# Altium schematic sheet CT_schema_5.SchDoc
size 188 x 165 mm
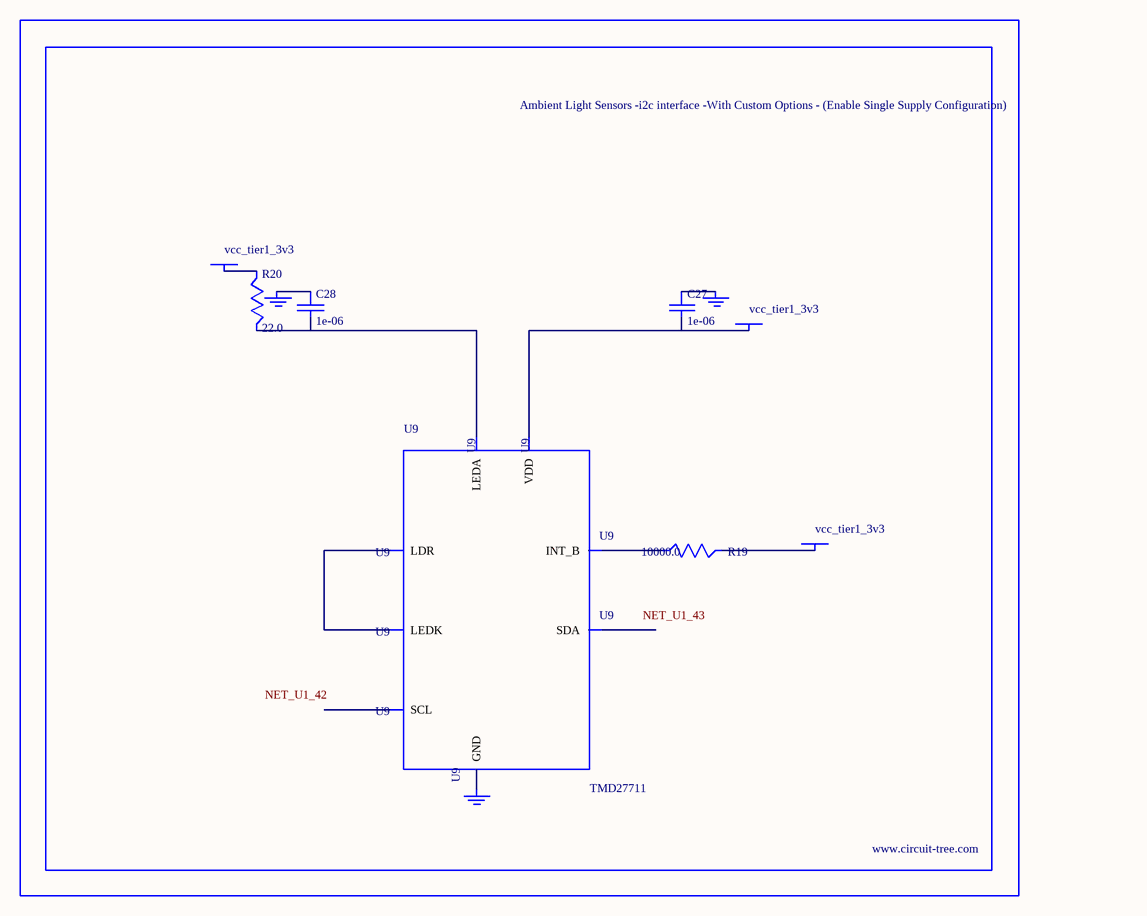
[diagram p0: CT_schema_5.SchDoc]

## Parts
BORDER4  (no value)
C27  1e-06  [C0603]
C28  1e-06  [C0603]
GND_INSTANCE_4_0  (no value)
GND_INSTANCE_4_1  (no value)
GND_INSTANCE_4_2  (no value)
POWER_INSTANCE_4_0  vcc_tier1_3v3
POWER_INSTANCE_4_1  vcc_tier1_3v3
POWER_INSTANCE_4_2  vcc_tier1_3v3
R19  10000.0  [R0603]
R20  22.0  [R0603]
U9  TMD27711  [SMD-8]

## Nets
NetC27_1: C27.1 GND_INSTANCE_4_0.0(GND)
NetC27_2: C27.2 POWER_INSTANCE_4_0.0(PWR) U9.1(VDD)
NetC28_1: C28.1 GND_INSTANCE_4_1.0(GND)
NetC28_2: C28.2 R20.2 U9.4(LEDA)
NetGND_INSTANCE_4_2_0: GND_INSTANCE_4_2.0(GND) U9.3(GND)
NetPOWER_INSTANCE_4_1_0: POWER_INSTANCE_4_1.0(PWR) R20.1
NetPOWER_INSTANCE_4_2_0: POWER_INSTANCE_4_2.0(PWR) R19.2
NetR19_1: R19.1 U9.7(INT_B)
NetU9_5: U9.5(LEDK) U9.6(LDR)

Not connected (* = marked no-connect by the designer): U9 2(SCL) 8(SDA)

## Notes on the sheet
- Labels drawn without touching a wire or pin: NET_U1_42, NET_U1_43

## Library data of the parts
BORDER4 = BORDER_PAGE4
C27 C28 = C0603C105K3RACTU
GND_INSTANCE_4_0-GND_INSTANCE_4_2 = GND
POWER_INSTANCE_4_0-POWER_INSTANCE_4_2 = PWR
R19 = RC0603JR-0710KL
R20 = RC0603JR-0722RL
